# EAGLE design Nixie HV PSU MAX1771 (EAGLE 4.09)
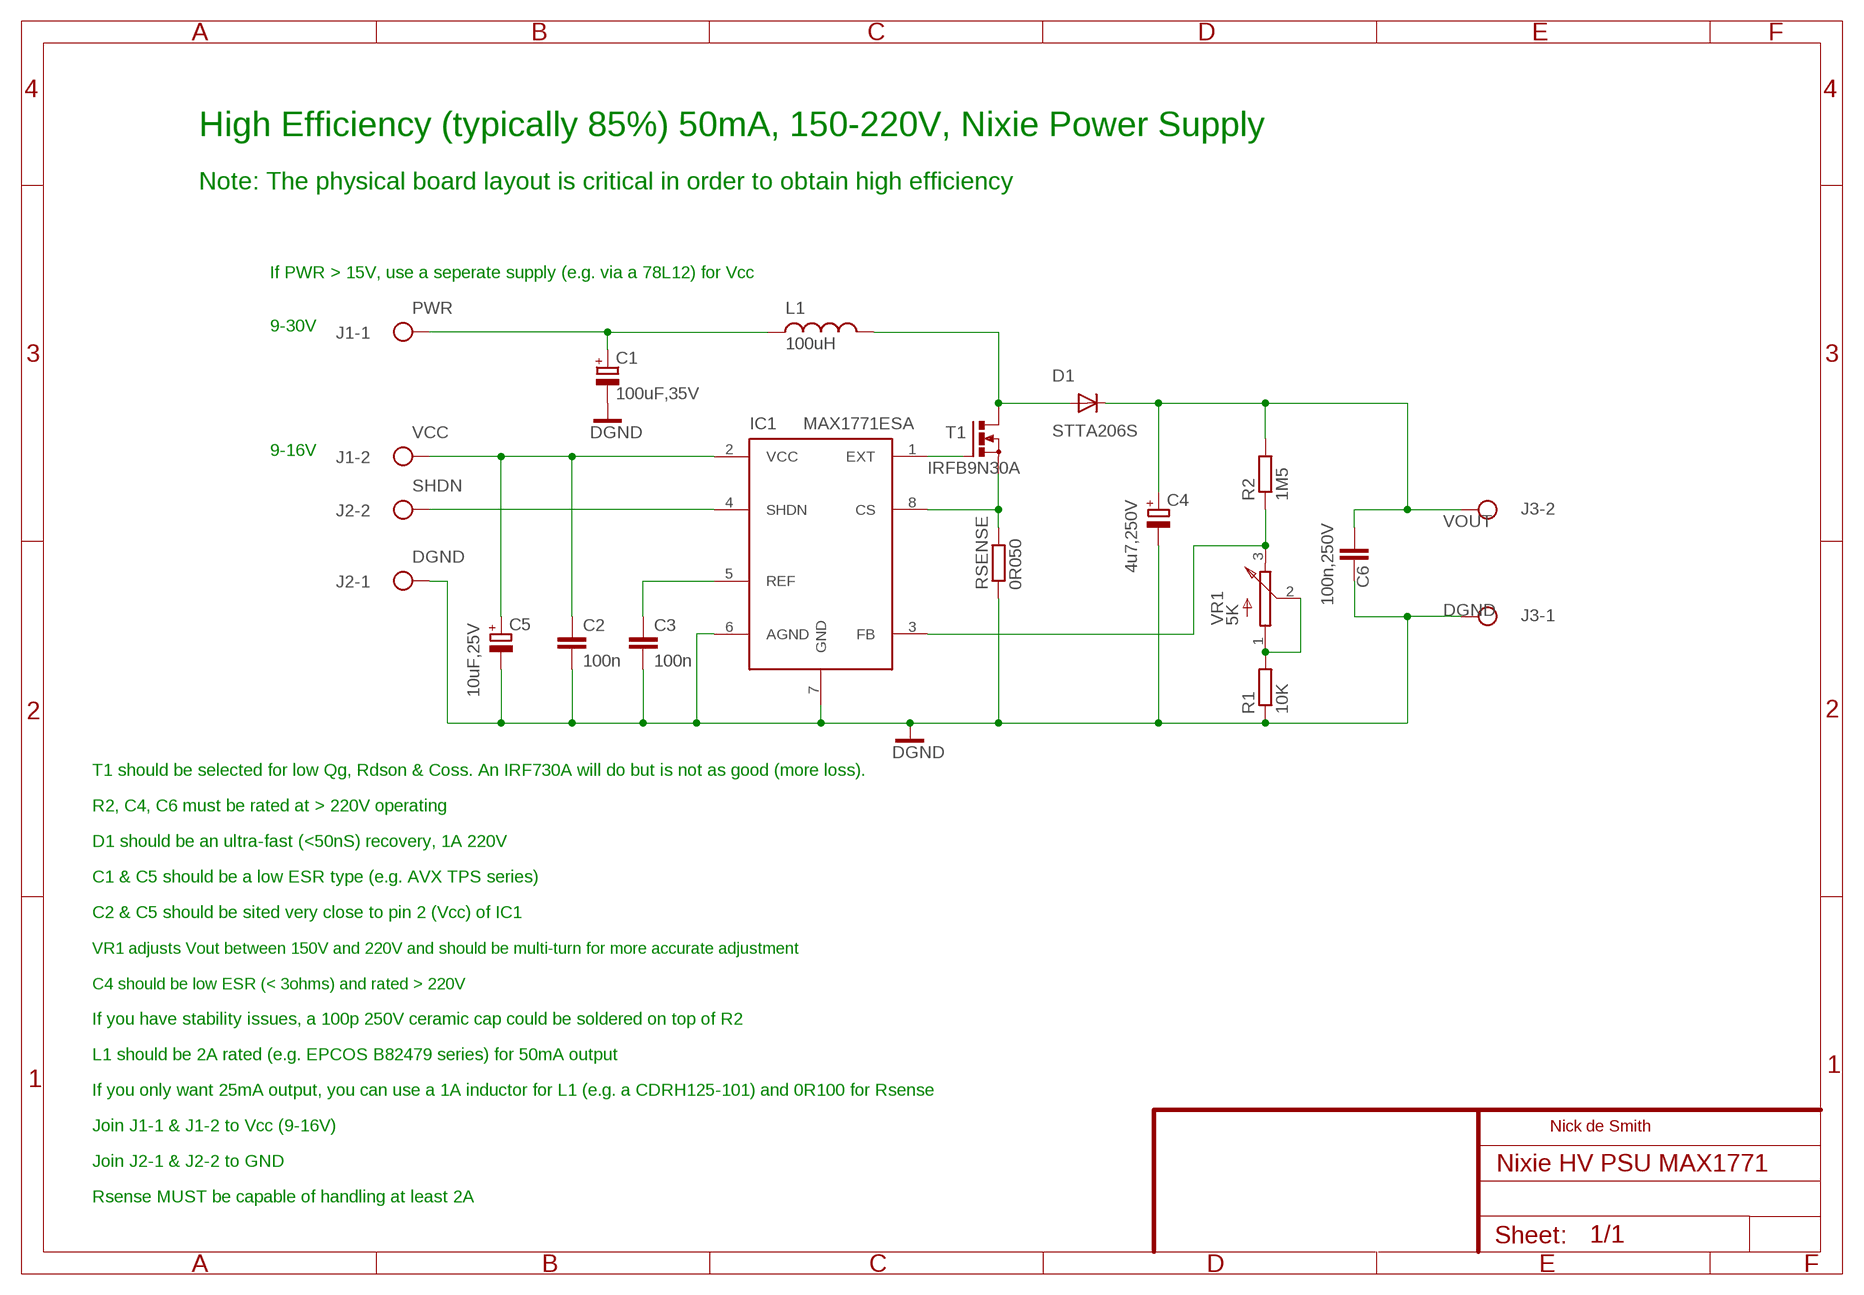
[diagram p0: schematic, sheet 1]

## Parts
C1  100uF,35V  C-POL-EU7343  [C-EIA-7343]
C2  100n  C-EUC0805  [C0805]
C3  100n  C-EUC0805  [C0805]
C4  4u7,250V  C-POL-EU-NICHICON-UJ-12  [NICHICON-UJ-12]
C5  10uF,25V  C-POL-EU7343  [C-EIA-7343]
C6  100n,250V  C-EU-2420  [C2420]
D1  STTA206S  DIODE-SMC  [SMC]
IC1  MAX1771ESA  [SO-8]
J1  TERM-BLOCK-2-02IN  [SCREW-2-02]
J2  TERM-BLOCK-2-02IN  [SCREW-2-02]
J3  TERM-BLOCK-2-02IN  [SCREW-2-02]
L1  100uH  L-SMT-POWER-B82479  [L-B82479]
R1  10K  R-EU_R0805  [R0805]
R2  1M5  R-EU_R2512  [R2512]
RSENSE  0R050  R-EU_R2010  [R2010]
T1  IRFB9N30A  IRF740  [TO220BV]
VR1  5K  TRIMPOT-3214W  [BOURNS-3214W]

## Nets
DGND [power]: C1.- C2.2 C3.2 C4.1(-) C5.- C6.P$2 IC1.6(AGND) IC1.7(GND) J2.1 J3.1 R1.1 RSENSE.1
EXT: IC1.1(EXT) T1.G
N$2: IC1.8(CS) RSENSE.2 T1.S
N$3: R1.2 VR1.1(A) VR1.2(W)
N$8: IC1.3(FB) R2.1 VR1.3(B)
N$15 [power]: D1.A L1.P$2 T1.D
N$17: C3.1 IC1.5(REF)
PWR [power]: C1.+ J1.1 L1.P$1
SHDN: IC1.4(SHDN) J2.2
VCC [power]: C2.1 C5.+ IC1.2(VCC) J1.2
VOUT [power]: C4.2(+) C6.P$1 D1.C J3.2 R2.2

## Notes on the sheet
- High Efficiency (typically 85%) 50mA, 150-220V, Nixie Power Supply
- Note: The physical board layout is critical in order to obtain high efficiency
- If PWR > 15V, use a seperate supply (e.g. via a 78L12) for Vcc
- 9-30V
- 9-16V
- T1 should be selected for low Qg, Rdson & Coss. An IRF730A will do but is not as good (more loss).
- R2, C4, C6 must be rated at > 220V operating
- D1 should be an ultra-fast (<50nS) recovery, 1A 220V
- C1 & C5 should be a low ESR type (e.g. AVX TPS series)
- C2 & C5 should be sited very close to pin 2 (Vcc) of IC1
- VR1 adjusts Vout between 150V and 220V and should be multi-turn for more accurate adjustment
- C4 should be low ESR (< 3ohms) and rated > 220V
- If you have stability issues, a 100p 250V ceramic cap could be soldered on top of R2
- L1 should be 2A rated (e.g. EPCOS B82479 series) for 50mA output
- If you only want 25mA output, you can use a 1A inductor for L1 (e.g. a CDRH125-101) and 0R100 for Rsense
- Join J1-1 & J1-2 to Vcc (9-16V) | Nick de Smith
- Join J2-1 & J2-2 to GND
- Rsense MUST be capable of handling at least 2A

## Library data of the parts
C1 C5 = nick:C-POL-EU7343: Capacitor, Tantalum, EU 7343 case, polarised
C2 C3 = rcl:C-EU: CAPACITOR, European symbol
C4 = nick:C-POL-EU: Capacitor, Tantalum, EU 7343 case, polarised
C6 = nick:C-EU
D1 = diode:DIODE-: DIODE
IC1 = nick:MAX1771
J1-J3 = nick:TERM-BLOCK-2
L1 = nick:L-SMT-POWER: SMT power inductors
R1 R2 RSENSE = rcl:R-EU_: RESISTOR, European symbol
T1 = transistor-power:IRF740: N-CHANNEL MOS FET
VR1 = nick:TRIMPOT

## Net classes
1 power: width 0.762 mm, drill 0.508 mm

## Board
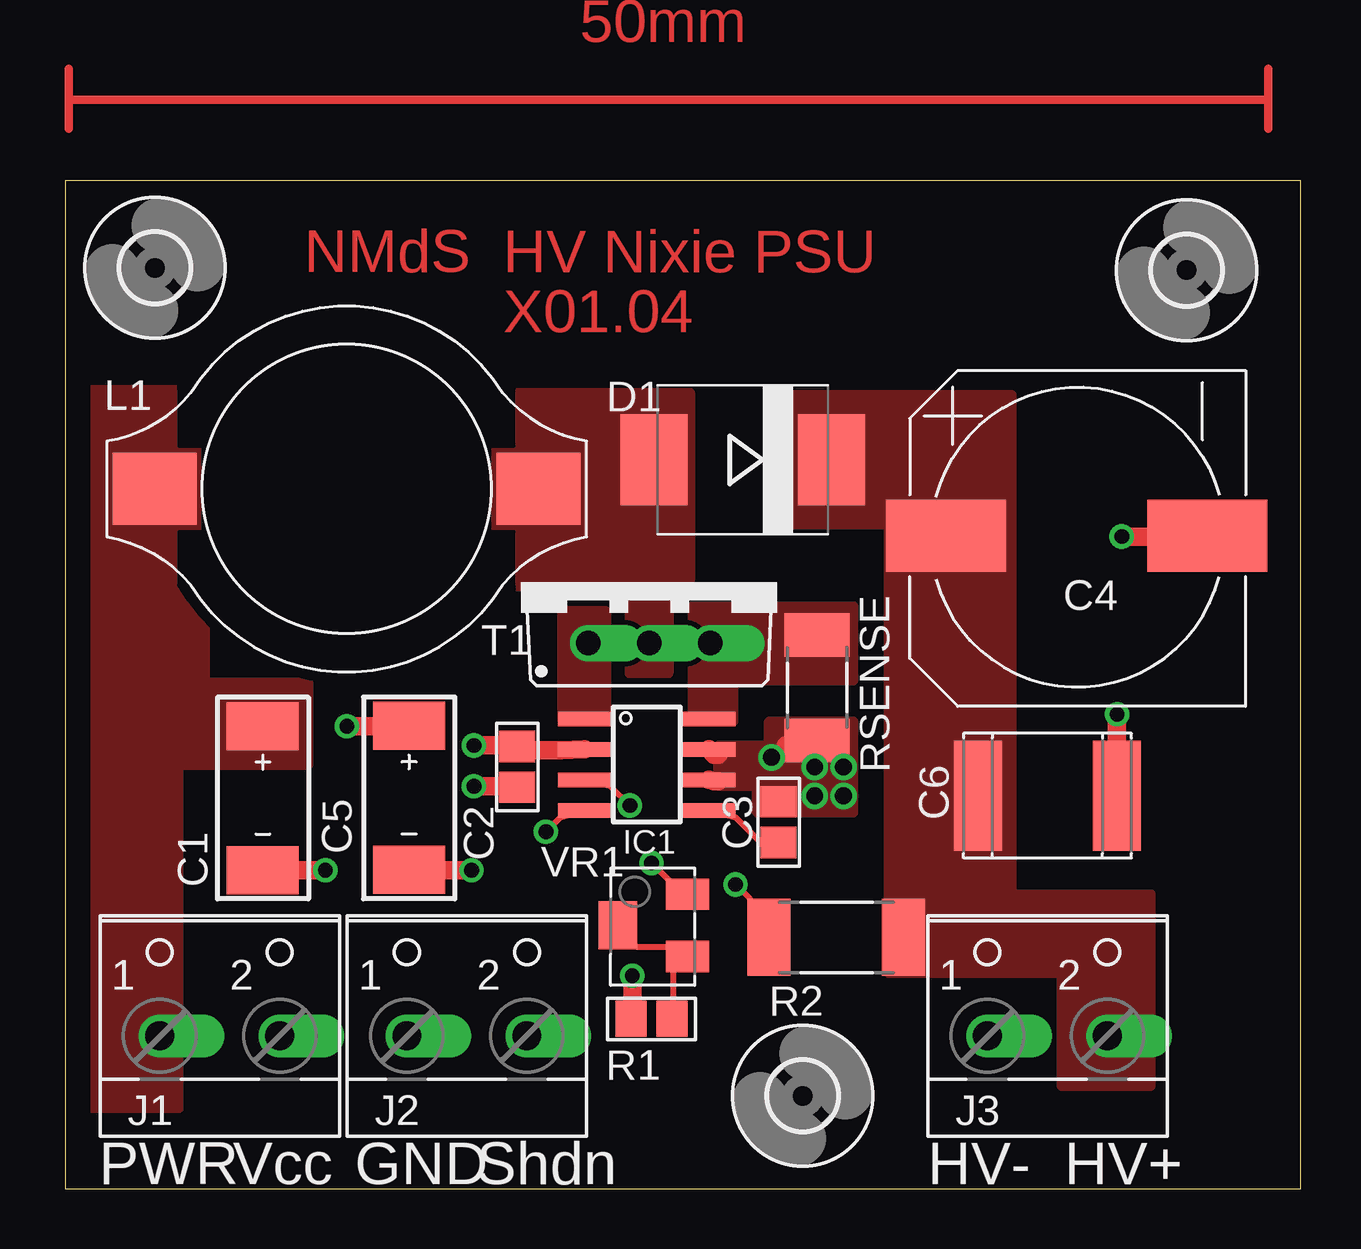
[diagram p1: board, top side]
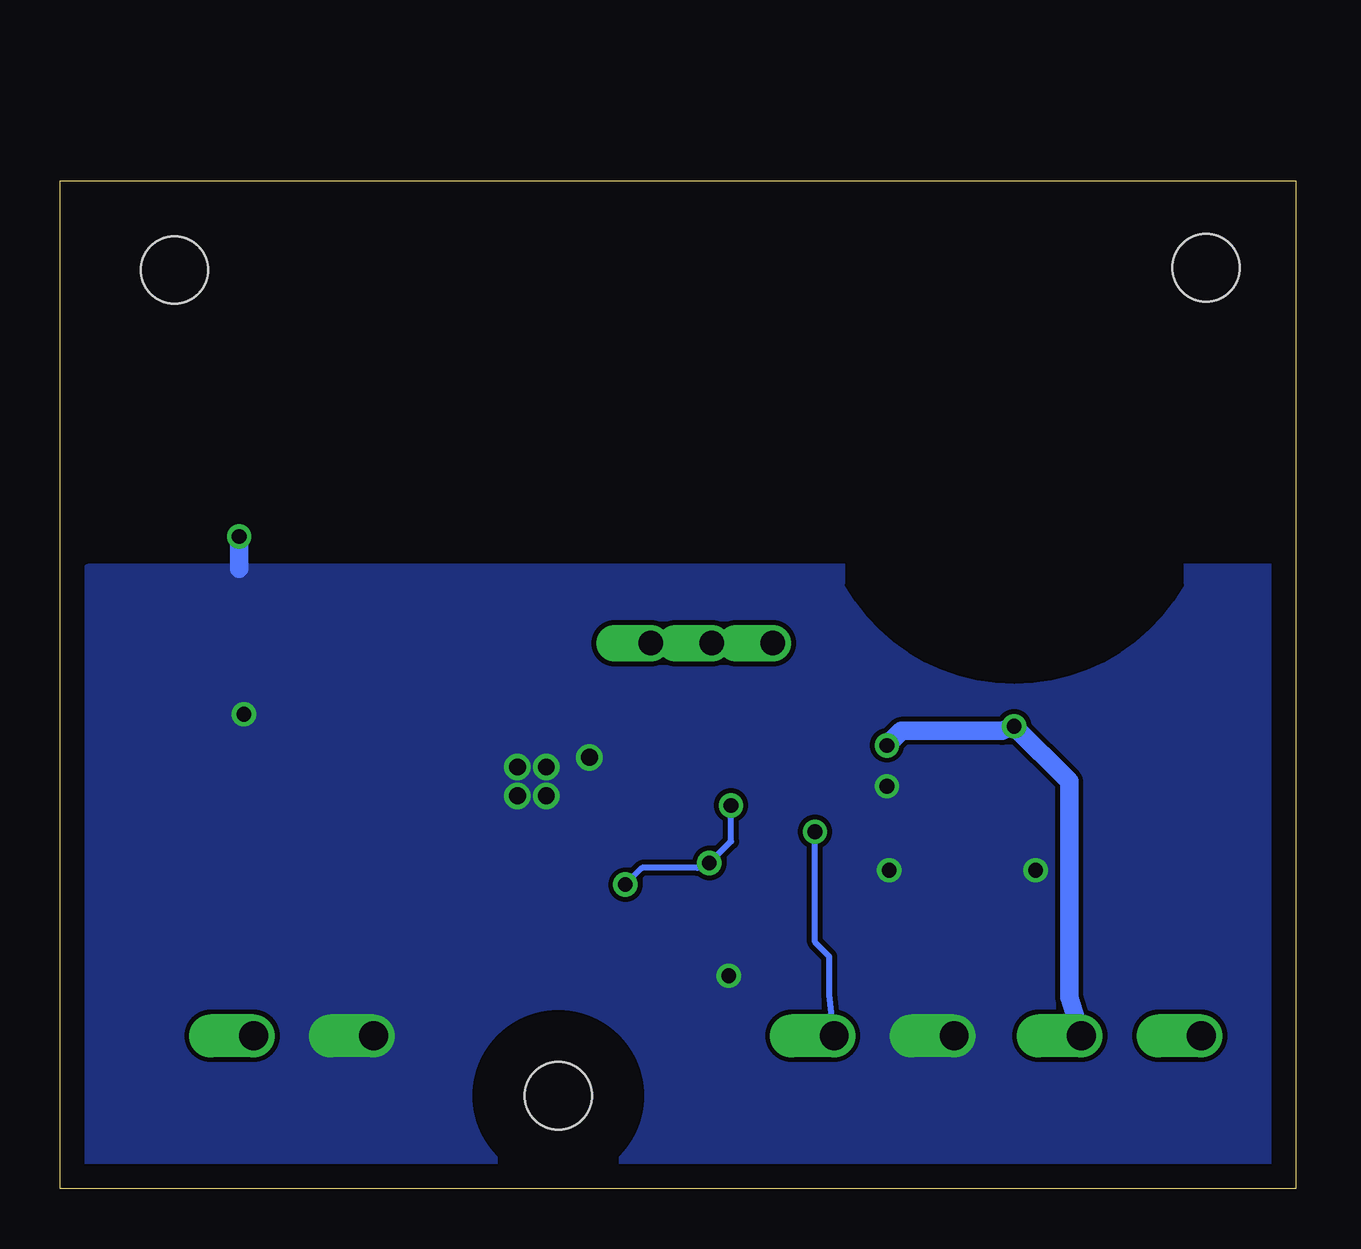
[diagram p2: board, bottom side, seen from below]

Size 51.5 x 42 mm. Coordinates in mm from the lower left corner, seen from the top.
Outline: 0,0 51.5,0 51.5,42 0,42 0,0
Copper layers used: Top, Bottom

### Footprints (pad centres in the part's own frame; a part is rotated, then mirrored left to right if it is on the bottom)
C-EIA-7343 = smd 2 x 3: + -3,0; - 3,0
C0805 = smd 1.3 x 1.5: 1 -0.85,0; 2 0.85,0
NICHICON-UJ-12 = smd 3 x 5: 1 -2.4,-7.6; 2 -2.4,3.3
C2420 = smd 2 x 4.6: P$1 2.9,0; P$2 -2.9,0
SMC = smd 2.8 x 3.8: A 3.7,0; C -3.7,0
SO-8 = smd 0.6 x 2.2: 1 -1.905,-2.6; 2 -0.635,-2.6; 3 0.635,-2.6; 4 1.905,-2.6; 5 1.905,2.6; 6 0.635,2.6; 7 -0.635,2.6; 8 -1.905,2.6
SCREW-2-02 = drill 1.194 offset: 1 -2.5,0; 2 2.5,0
L-B82479 = smd 3.5 x 3: P$1 -8,0; P$2 8,0
R0805 = smd 1.3 x 1.5: 1 -0.85,0; 2 0.85,0
R2512 = smd 1.8 x 3.2: 1 -2.8,0; 2 2.8,0
R2010 = smd 1.8 x 2.7: 1 -2.2,0; 2 2.2,0
TO220BV = drill 1.016 offset: D 0,-2.54; G -2.54,-2.54; S 2.54,-2.54
2,8 = hole 2.8: 0,0
BOURNS-3214W = smd 1.8 x 1.3: 1 1.4,-1.3; 3 1.4,1.3 | smd 1.6 x 2: 2 -1.5,0

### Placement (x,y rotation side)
C1  8.23,16.27 270 top
C2  18.83,17.57 270 top
C3  29.73,15.27 90 top
C4  39.99,29.6 90 top
C5  14.32,16.28 270 top
C6  40.93,16.37 180 top
D1  28.23,30.37 180 top
IC1  24.23,17.67 270 top
J1  6.43,6.37 0 top
J2  16.73,6.37 0 top
J3  40.93,6.37 0 top
L1  11.72,29.16 0 top
R1  24.43,7.07 0 top
R2  32.13,10.47 0 top
RSENSE  31.33,20.87 90 top
T1  24.33,25.27 0 top
U$2  [2,8]  3.73,38.37 0 top
U$3  [2,8]  46.73,38.27 0 top
U$4  [2,8]  30.73,3.87 0 top
VR1  24.53,10.97 0 top

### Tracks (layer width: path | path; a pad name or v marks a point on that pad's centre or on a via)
DGND  (via drill 0.61, 0.7)
  Top 0.762: v23.63,8.87 23.63,7.77 R1.1 | v17.03,16.77 18.13,16.77 C2.2 | IC1.6 27.03,16.97 27.23,16.97 | IC1.7 27.03,18.07 27.23,18.07 | 30.03,18.47 RSENSE.1 | v10.83,13.27 9.73,13.27 C1.- | v16.93,13.27 15.73,13.27 C5.- | v43.83,19.77 43.83,18.67 C6.P$2 | v44.03,27.17 45.13,27.17 C4.1
  Bottom 0.762: 44.03,25.83 v44.03,27.17
  other vias: 29.43,17.97 31.23,17.57 32.43,17.57 32.43,16.37 31.23,16.37
  pour Bottom (isolate 0.01, rank 3, no thermals): 0.43,25.83 50.33,25.83 50.33,0.57 0.43,0.57
  pour Top (no thermals): 27.23,16.77 27.23,18.47 29.33,18.47 29.33,19.47 32.83,19.47 32.83,15.67 28.83,15.67 28.83,16.77
EXT
  pour Top (no thermals): 20.73,24.07 22.53,24.07 22.53,19.47 20.73,19.47
N$1
  Top 0.358: 0.13,45.37 0.13,46.67 | 0.13,44.17 0.13,45.37 | 0.13,45.37 50.13,45.37 | 50.13,45.37 50.13,46.67 | 50.13,45.37 50.13,44.17
N$2
  pour Top (no thermals): 26.16,19.47 26.16,24.27 32.83,24.27 32.83,21.17 27.83,21.17 27.83,19.47
N$3
  Top 0.254: R1.2 25.33,7.77 25.33,9.07 VR1.1 25.13,10.07 23.83,10.07 VR1.2
N$8  (via drill 0.61)
  Top 0.254: v23.53,15.97 22.73,16.77 IC1.3 | v24.43,13.57 25.13,12.87 VR1.3 | v27.93,12.67 28.53,12.07 R2.1
  Bottom 0.254: v23.53,15.97 23.53,14.47 v24.43,13.57 24.93,13.37 27.23,13.37 v27.93,12.67
N$15
  pour Top (no thermals): 17.63,33.17 26.03,33.17 26.03,25.37 25.13,25.37 25.13,21.47 23.53,21.47 23.53,25.07 17.63,25.07
N$17
  Top 0.254: IC1.5 27.93,15.47 29.03,14.37 C3.1
PWR
  pour Top (isolate 0.01, rank 2, no thermals): 4.73,17.67 10.13,17.67 10.13,21.07 5.83,21.07 5.83,33.27 0.83,33.27 0.83,3.37 4.73,3.37
SHDN  (via drill 0.61)
  Top 0.254: v20.03,14.87 20.63,15.47 IC1.4
  Bottom 0.254: v20.03,14.87 20.03,10.27 19.43,9.67 19.43,8.07 J2.2
VCC  (via drill 0.61)
  Top 0.762: IC1.2 20.63,18.27 19.53,18.27 C2.1 18.13,18.47 v17.03,18.47 | v11.73,19.27 12.83,19.27 C5.+
  Bottom 0.762: J1.2 9.43,7.97 9.43,16.97 v11.73,19.27 12.23,19.07 16.43,19.07 v17.03,18.47
VOUT
  pour Top (isolate 0.01, rank 2, no thermals): 30.33,33.07 39.43,33.07 39.43,12.27 45.23,12.27 45.23,4.27 41.53,4.27 41.53,8.97 34.33,8.97 34.33,27.67 30.33,27.67

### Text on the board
Top: 50mm | NMdS | HV Nixie PSU | X01.04
tPlace: PWR | Vcc | GND | Shdn | HV- | HV+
